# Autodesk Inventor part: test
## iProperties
Shininess: 65.0
Angle Display Precision: 2
Document Length Units: 11269
Document Angle Units: 11279
Document Time Units: 11290
Document Mass Units: 11283
Document Length Units Precision: 3
Document Angle Units Precision: 2
Created: 2002-02
Part Number: test
Document SubType Name: Modeling
Designer: ***
Density: 0.0
Volumn: 0.0
Area: 0.0
PropertySet Name: Model Information
Control State: 0
Master: False
Checked Out: False
Author: ***
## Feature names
1. Extrusion1
2. Hole1
3. Circular Pattern1
